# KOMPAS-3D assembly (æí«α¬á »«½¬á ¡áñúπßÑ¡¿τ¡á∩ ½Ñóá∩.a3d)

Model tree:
1. Эскиз:1

Referenced files in D:\МОДЕЛЬ ТАНКА Т90\ДЕТАЛИ\КОРПУС\МЕТАЛЛ\КОРПУС ЛИТОЙ\: надгусеничная полка левая.m3d, брызговик левый.m3d, глушитель.m3d
Referenced files in D:\МОДЕЛЬ ТАНКА Т90\ДЕТАЛИ\КОРПУС\МЕТАЛЛ\КОРПУС ШТАМПОВКА\БАКИ\: Сборка бак левый 1.a3d, Сборка бак левый 2.a3d, Сборка бак левый 3.a3d, Сборка бак левый 5.a3d, бак левый 4.m3d
Referenced files in D:\МОДЕЛЬ ТАНКА Т90\СБОРКИ\СБОРКА ЛИТЬЕ СТАРАЯ\: Сборка экран левый.a3d
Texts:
  Сборка полка надгусеничная левая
